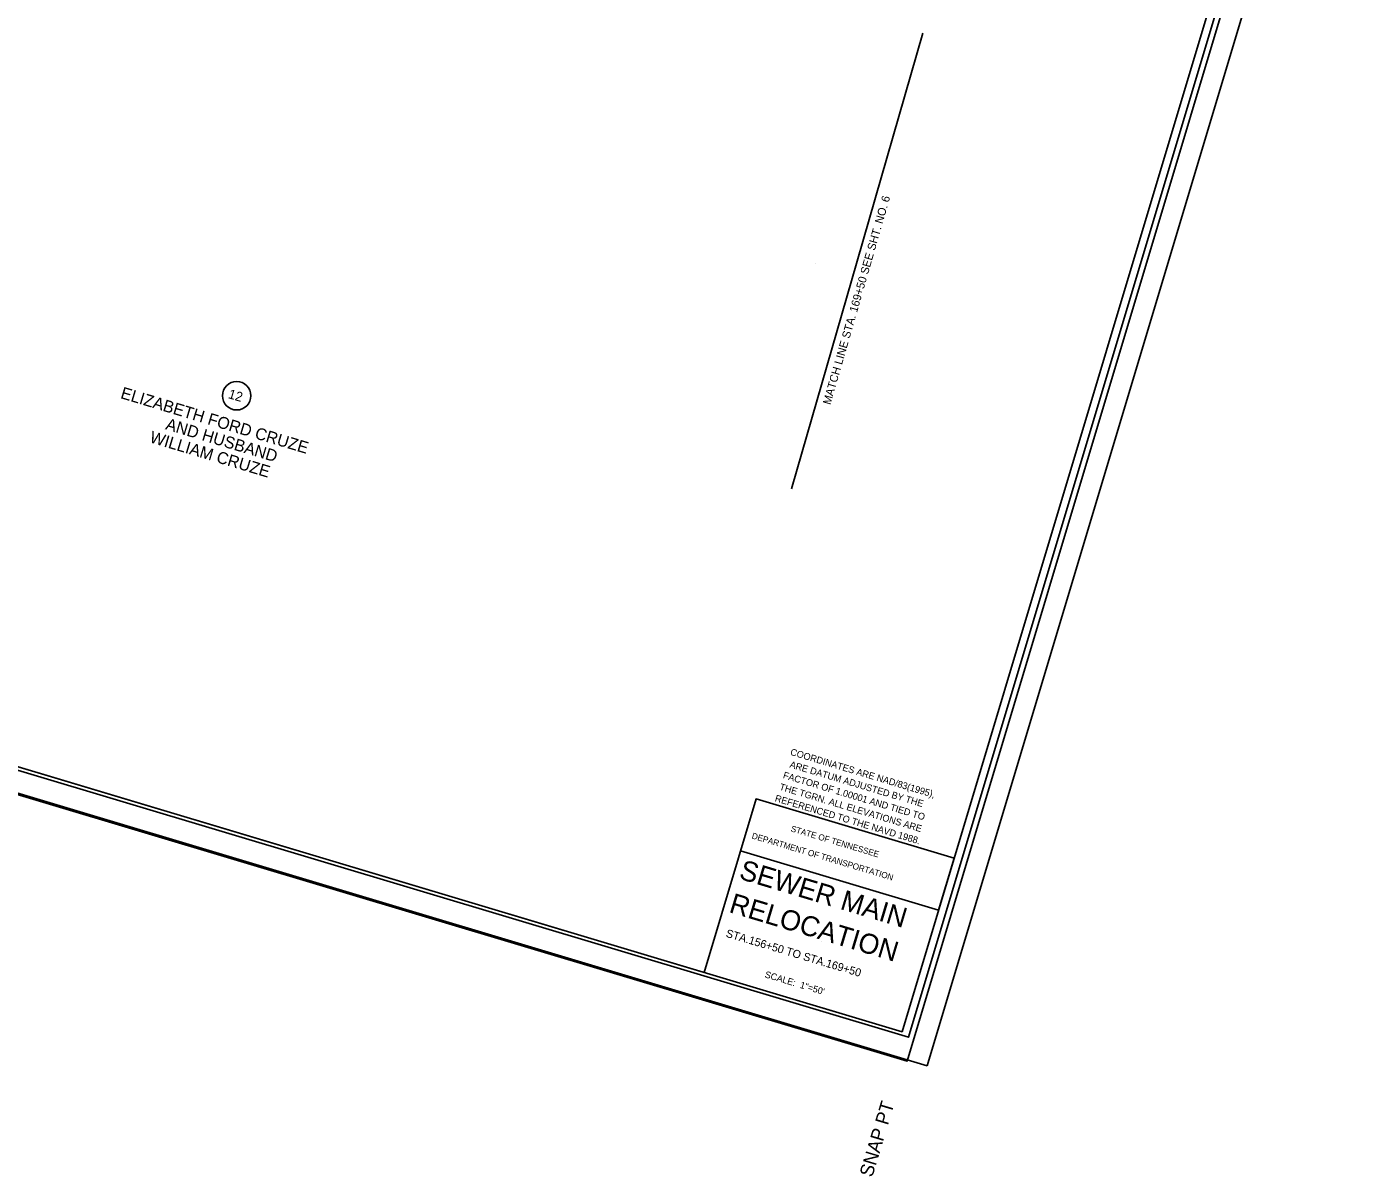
# Model space of a CAD drawing. Extents: x 2627582 to 2629622, y 568931 to 570612.
# Drawn here: x 2628642 to 2629619, y 568931 to 569779 of the extents above; entities that cross this region are included whole.
import ezdxf

# ---------------------------------------------------------------- set-up
doc = ezdxf.new("R2010")
doc.units = 0
for name, color, linetype in [('DESIGN - CENTERLINE - Proposed Text', 7, 'Continuous'), ('DESIGN - SCRATCH - User 1', 7, 'Continuous'), ('DESIGN - SHEET - Corner Text', 7, 'Continuous'), ('DESIGN - SHEET - Light Grid', 7, 'Continuous'), ('DESIGN - SHEET - Linework', 7, 'Continuous'), ('DESIGN - SHEET - Plot Shape', 7, 'Continuous'), ('SURVEY - PROPERTY - Owners', 7, 'Continuous'), ('SURVEY - PROPERTY - Tract Numbers', 7, 'Continuous')]:
    doc.layers.add(name, color=color, linetype=linetype)

msp = doc.modelspace()

# ---------------------------------------------------------------- linework, layer by layer
at = {"layer": 'DESIGN - CENTERLINE - Proposed Text'}
msp.add_lwpolyline([(2629206.17, 569438.02), (2629254.54, 569606.2), (2629302.91, 569774.39)], dxfattribs=at)
at = {"layer": 'DESIGN - SCRATCH - User 1'}
for p, q in [((2629223.72, 569604.66), (2629223.72, 569604.66)), ((2629228.13, 569104.12), (2629228.13, 569104.12))]:
    msp.add_line(p, q, dxfattribs=at)
at = {"layer": 'DESIGN - SHEET - Light Grid'}
msp.add_lwpolyline([(2627697.64, 569511.43), (2629292.52, 569033.35), (2629595.46, 570043.92), (2628000.57, 570522.01)], close=True, dxfattribs=at)
at = {"layer": 'DESIGN - SHEET - Linework'}
for p in [(2629618.55, 570053.91), (2627582.11, 569529.15)]:
    msp.add_line(p, (2629306.31, 569012.3), dxfattribs=at)
for points in [[(2628081.32, 570495.19), (2627779.83, 569489.41), (2629287.73, 569037.39), (2629589.23, 570043.18), (2628081.32, 570495.19)], [(2629141.66, 569081.18), (2629180.03, 569209.2), (2629326.11, 569165.42), (2629314.62, 569127.1), (2629168.55, 569170.89)]]:
    msp.add_lwpolyline(points, dxfattribs=at)
at = {"layer": 'DESIGN - SHEET - Plot Shape'}
for points in [[(2627975.91, 570547.35), (2629604.32, 570059.22), (2629291.51, 569015.7), (2627663.1, 569503.83)], [(2627999.85, 570519.61), (2629589.23, 570043.18), (2629287.73, 569037.39), (2627698.36, 569513.83)]]:
    msp.add_lwpolyline(points, close=True, dxfattribs=at)
at = {"layer": 'SURVEY - PROPERTY - Tract Numbers'}
msp.add_circle((2628796.81, 569506.74), 10.5, dxfattribs=at)

# ---------------------------------------------------------------- texts
at = {"layer": 'DESIGN - CENTERLINE - Proposed Text'}
msp.add_text('MATCH LINE STA. 169+50 SEE SHT. NO. 6', height=6, rotation=73.95539, dxfattribs=at).set_placement((2629234.84, 569499.71))
at = {"layer": 'DESIGN - SHEET - Corner Text'}
for s, height, rotation, p in [('COORDINATES ARE NAD/83(1995),', 5.0001, 343.31329, (2629204.81, 569241.81)), ('ARE DATUM ADJUSTED BY THE', 5.0001, 343.31329, (2629204.38, 569232.55)), ('THE TGRN. ALL ELEVATIONS ARE', 5.0001, 343.31329, (2629196.82, 569216.02)), ('FACTOR OF 1.00001 AND TIED TO', 5.0001, 343.31329, (2629199.47, 569224.62)), ('REFERENCED TO THE NAVD 1988.', 5.0001, 343.31329, (2629193.49, 569207.62)), ('DEPARTMENT OF TRANSPORTATION', 4.5, 343.31329, (2629176.43, 569180.11)), ('STATE OF TENNESSEE', 4.5, 343.31329, (2629205.25, 569185.36)), ('SEWER MAIN', 14.764, 343.31329, (2629166.72, 569150.47)), ('RELOCATION', 14.764, 343.31329, (2629159.32, 569125.79)), ('STA.156+50 TO STA.169+50', 5.9055, 343.31329, (2629157.26, 569107.55)), ('SCALE:  1"=50\'', 4.9215, 343.31329, (2629186.02, 569077.6)), ('SNAP PT  ', 10, 73.31329, (2629265.67, 568929.49))]:
    msp.add_text(s, height=height, rotation=rotation, dxfattribs=at).set_placement(p)
at = {"layer": 'SURVEY - PROPERTY - Owners'}
for s, p in [('ELIZABETH FORD CRUZE', (2628710.57, 569505.09)), ('AND HUSBAND', (2628743.75, 569482.09)), ('WILLIAM CRUZE', (2628732.02, 569472.56))]:
    msp.add_text(s, height=8.75, rotation=343.31329, dxfattribs=at).set_placement(p)
at = {"layer": 'SURVEY - PROPERTY - Tract Numbers'}
msp.add_text('12', height=7, rotation=343.31329, dxfattribs=at).set_placement((2628790.06, 569505.11))

doc.saveas('drawing.dxf')
